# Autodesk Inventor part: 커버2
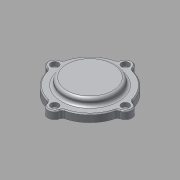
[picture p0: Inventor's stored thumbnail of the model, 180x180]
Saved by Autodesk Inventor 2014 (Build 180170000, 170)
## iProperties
Company: 한국ATC센터
Created: 2015-12
Part Number: 커버2
Document SubType Name: Modeling
Designer: mdu
Density: 2.71 g/cm^3
Material: 알루미늄 6061
Mass: 152.219 g
Surface Area: 146.729 cm^2
Volume: 56.1694 cm^3
Appearance: Aluminum - Flat
Author: mdu
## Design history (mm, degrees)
sketch "스케치1"
  geometry: C1 r 1.621 at (0, 6.75) reference; C2 r 1.621 at (-37, -30.25) reference; C3 r 1.621 at (0, -67.25) reference; C4 r 1.621 at (37, -30.25) reference; C5 r 10 at (0, -30.25) reference; C6 r 12 at (0, -30.25); C7 r 24.5 at (0, -30.25) reference; A1 r 3 centre (-38.77, -20.408) between (-38.239, -23.361) and (-35.862, -21.146) reference; A2 r 7 centre (-37, -30.25) between (-38.239, -23.361) and (-38.239, -37.139) reference; A3 r 3 centre (-38.77, -40.092) between (-35.862, -39.354) and (-38.239, -37.139) reference; A4 r 37 centre (0, -30.25) between (-35.862, -39.354) and (-9.104, -66.113) reference; A5 r 3 centre (-9.842, -69.02) between (-6.889, -68.489) and (-9.104, -66.113) reference; A6 r 7 centre (0, -67.25) between (-6.889, -68.489) and (6.889, -68.489) reference; A7 r 3 centre (9.842, -69.02) between (9.104, -66.112) and (6.889, -68.489) reference; A8 r 37 centre (0, -30.25) between (9.104, -66.112) and (35.863, -39.354) reference; A9 r 3 centre (38.77, -40.092) between (38.239, -37.139) and (35.863, -39.354) reference; A10 r 7 centre (37, -30.25) between (38.239, -37.139) and (38.239, -23.361) reference; A11 r 3 centre (38.77, -20.408) between (35.863, -21.146) and (38.239, -23.361) reference; A12 r 37 centre (0, -30.25) between (35.863, -21.146) and (9.104, 5.612) reference; A13 r 3 centre (9.842, 8.52) between (6.889, 7.989) and (9.104, 5.612) reference; A14 r 7 centre (0, 6.75) between (6.889, 7.989) and (-6.889, 7.989) reference; A15 r 3 centre (-9.842, 8.52) between (-9.104, 5.612) and (-6.889, 7.989) reference; A16 r 37 centre (0, -30.25) between (-9.104, 5.612) and (-35.862, -21.146) reference; 1 further point
  constraints: 1 centre point, 1 coincident
  dimensions: "d2" = 2 radial gap between concentric circles of C6 C5
extrude "돌출1" new body sketch "스케치1" distance "d0" = 8; taper "d1" = 0 deg
sketch "스케치2"
  geometry: C1 r 23.5 at (0, -30.25) reference; C2 r 12 at (0, -30.25) reference; 1 further point
extrude "돌출2" join sketch "스케치2" distance "d4" = 5; taper "d5" = 0 deg
sketch "스케치3"
  geometry: C1 r 23.5 at (0, 0) reference; C2 r 20.5 at (0, 0); 1 further point
  constraints: 1 centre point
  dimensions: "d6" = 3 radial gap between concentric circles of C2 C1
node "작업 평면1"
extrude "돌출3" join sketch "스케치3" stored distance "d7" = 5; taper "d8" = 0 deg
fillet "모깎기1" dims "d9" = 3
sketch "스케치4"
  geometry: C1 r 12 at (0, -30.25) reference; C2 r 27 at (0, -30.25); 1 further point
  constraints: 1 centre point
  dimensions: "d10" = 15 radial gap between concentric circles of C1 C2
extrude "돌출4" join sketch "스케치4" distance "d11" = 7; taper "d12" = 0 deg
fillet "모깎기2" dims "d13" = 3
chamfer "모따기1" distance "d14" = 1; stored, may be unused: second distance "d15" = 2, angle "d16" = 45 deg
node "작업점1"
  node "작업축1"
chamfer "모따기2" distance "d24" = 1; stored, may be unused: second distance "d25" = 2, angle "d26" = 45 deg
hole "구멍6" diameter "d43" = 4.5; stored, may be unused: countersink angle "d47" = 90 deg, drill point angle "d49" = 118 deg; dims "d41" = 10, "d42" = 10, "d44" = 6, "d45" = 8, "d46" = 4.4, "d48" = 8
fillet "모깎기4" dims "d60" = 3
node "솔리드1"
pattern_circular "원형 패턴1" dims angle "d51" = 360 deg
node "참조1"
node "참조2"
